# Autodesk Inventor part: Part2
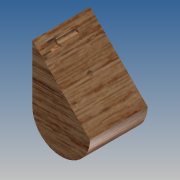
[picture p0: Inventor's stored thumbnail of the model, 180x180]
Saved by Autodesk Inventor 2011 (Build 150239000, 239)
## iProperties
Created: 2011-01
Part Number: Part2
Document SubType Name: Modeling
Designer: Microsoft
Density: 1 g/cm^3
Author: Microsoft
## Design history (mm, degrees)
sketch "Sketch1"
  geometry: L1 (9.525, 0)-(9.525, 19.05); L2 (-9.525, 19.05)-(-9.525, 0); L3 (-9.525, 19.05)-(9.525, 0); A1 r 9.525 centre (0, 0) between (-9.525, 0) and (9.525, 0); A2 r 9.525 centre (0, 19.05) between (9.525, 19.05) and (-9.525, 19.05); 1 further point
  constraints: 6 end point, 4 point on circle, 3 tangent, 2 centre point, 1 coincident, 1 vertical alignment
  dimensions: "d3" = 9.525 radius of A2; "d4" = 9.525 radius of A1; "d5" = 19.05 distance of L1.start L1.end; "d6" = 19.05 distance of point (0, 0) A2.centre
extrude "Extrusion1" new body sketch "Sketch1" distance "d7" = 19.05; taper "d8" = 0 deg
sketch "Sketch2"
  geometry: L1 (13.47, 0)-(13.47, 19.05) reference; C1 r 0.794 at (13.47, 9.525); 1 further point
  constraints: 1 centre point, 1 midpoint
  dimensions: "d9" = 1.5875 diameter of C1
extrude "Extrusion2" cut sketch "Sketch2" distance "d10" = 6.35; taper "d11" = 0 deg
sketch "Sketch3"
  geometry: C1 r 0.794 at (0, 0) reference; C2 r 1.587 at (0, 0); 1 further point
  constraints: 1 centre point, 1 coincident
  dimensions: "d12" = 3.175 diameter of C2
extrude "Extrusion3" cut sketch "Sketch3" distance "d13" = 0.79375; taper "d14" = 0 deg
workplane "Work Plane1"
sketch "Sketch4"
  geometry: L1 (9.525, 19.05)-(-9.525, 0) reference; L2 (9.525, 0)-(9.525, 19.05) reference; L3 (9.525, 19.05)-(5.927, 22.648); L4 (9.525, 19.05)-(-9.525, 0) reference; C1 r 0.794 at (7.28, 16.805); A1 r 9.525 centre (0, 0) between (-9.525, 0) and (9.525, 0) reference; 1 further point
  constraints: 2 end point, 1 centre point, 1 perpendicular, 1 point on line
  dimensions: "d16" = 1.5875 diameter of C1; "d17" = 3.175 distance from line of L3 C1.centre
extrude "Extrusion4" cut sketch "Sketch4" distance "d18" = 6.35; taper "d19" = 0 deg
sketch "Sketch5"
  geometry: L1 (6.719, 16.244)-(7.841, 17.366) reference; C1 r 1.587 at (7.28, 16.805); A1 r 0.794 centre (7.28, 16.805) between (6.719, 16.244) and (7.841, 17.366) reference; 1 further point
  constraints: 1 centre point, 1 coincident
  dimensions: "d20" = 3.175 diameter of C1
extrude "Extrusion5" cut sketch "Sketch5" distance "d21" = 3.175; taper "d22" = 0 deg
body "Solid1"
node "Projected Loop1"
other parameters: "d15" = -6.35
